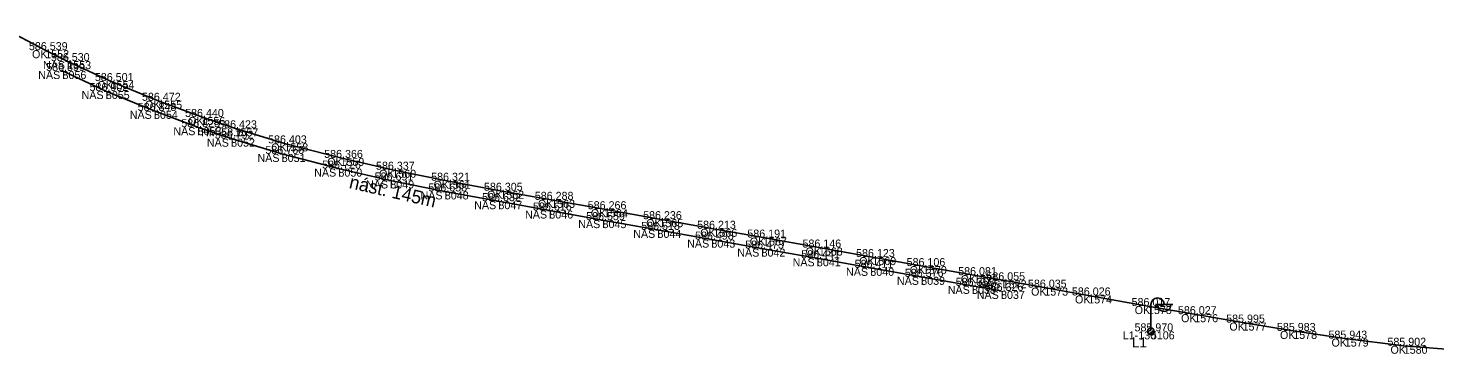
# Model space of a CAD drawing. Extents: x -631472 to -620808, y -1122356 to -1115125.
# Drawn here: x -623891.4 to -623680.4, y -1119630.6 to -1119581.7 of the extents above; entities that cross this region are included whole.
import ezdxf

# ---------------------------------------------------------------- set-up
doc = ezdxf.new("R2010")
doc.units = 0
for name, color, linetype in [('Vrstva 1', 7, 'Continuous'), ('Vrstva 14', 7, 'Continuous'), ('Vrstva 25', 7, 'Continuous'), ('Vrstva 26', 7, 'Continuous'), ('Vrstva 60', 7, 'Continuous'), ('Vrstva 61', 7, 'Continuous'), ('Vrstva 62', 7, 'Continuous')]:
    doc.layers.add(name, color=color, linetype=linetype)

msp = doc.modelspace()

# ---------------------------------------------------------------- linework, layer by layer
at = {"layer": 'Vrstva 1'}
msp.add_lwpolyline([(-623895.04, -1119581.75), (-623888.79, -1119585.05), (-623885.5, -1119586.69), (-623879, -1119589.68), (-623871.85, -1119592.64), (-623865.38, -1119595.06), (-623860.42, -1119596.76), (-623852.94, -1119599.02), (-623844.53, -1119601.2), (-623836.76, -1119602.97), (-623828.58, -1119604.62), (-623820.57, -1119606.12), (-623812.94, -1119607.48), (-623805.01, -1119608.89), (-623796.71, -1119610.38), (-623788.61, -1119611.82), (-623781.17, -1119613.14), (-623772.81, -1119614.63), (-623764.78, -1119616.06), (-623757.2, -1119617.41), (-623749.56, -1119618.77), (-623745.24, -1119619.54), (-623739.01, -1119620.64), (-623732.42, -1119621.81), (-623723.47, -1119623.4), (-623716.52, -1119624.62), (-623709.28, -1119625.88), (-623701.68, -1119627.13), (-623693.95, -1119628.28), (-623685.11, -1119629.35), (-623676.9, -1119629.99)], dxfattribs=at)
at = {"layer": 'Vrstva 14'}
msp.add_lwpolyline([(-623886.21, -1119588.17), (-623879.71, -1119591.17), (-623872.49, -1119594.15), (-623865.95, -1119596.59), (-623860.93, -1119598.31), (-623853.34, -1119600.6), (-623844.84, -1119602.8), (-623837.06, -1119604.58), (-623828.89, -1119606.22), (-623820.85, -1119607.68), (-623813.22, -1119609.08), (-623805.24, -1119610.52), (-623797, -1119611.98), (-623788.92, -1119613.44), (-623781.4, -1119614.79), (-623773.1, -1119616.24), (-623765.09, -1119617.67), (-623757.46, -1119619.02), (-623749.84, -1119620.37), (-623745.49, -1119621.13)], dxfattribs=at)
at = {"layer": 'Vrstva 25'}
for p, q in [((-623723.03, -1119626.69), (-623723.03, -1119623.19)), ((-623722.33, -1119623.19), (-623719.73, -1119623.19)), ((-623723.51, -1119627.34), (-623722.89, -1119626.72)), ((-623723.27, -1119627.63), (-623722.59, -1119626.95))]:
    msp.add_line(p, q, dxfattribs=at)
msp.add_circle((-623723.03, -1119627.19), 0.5, dxfattribs=at)
for centre, start, end in [((-623722.03, -1119623.19), 0, 180), ((-623721.03, -1119623.21), 179.2974, 0.7026)]:
    msp.add_arc(centre, 1, start, end, dxfattribs=at)
at = {"layer": 'Vrstva 60'}
for p, q in [((-623888.79, -1119585.05), (-623888.79, -1119585.05)), ((-623885.5, -1119586.69), (-623885.5, -1119586.69)), ((-623886.21, -1119588.17), (-623886.21, -1119588.17)), ((-623879, -1119589.68), (-623879, -1119589.68)), ((-623879.71, -1119591.17), (-623879.71, -1119591.17)), ((-623871.85, -1119592.64), (-623871.85, -1119592.64)), ((-623872.49, -1119594.15), (-623872.49, -1119594.15)), ((-623865.38, -1119595.06), (-623865.38, -1119595.06)), ((-623865.95, -1119596.59), (-623865.95, -1119596.59)), ((-623860.42, -1119596.76), (-623860.42, -1119596.76)), ((-623860.93, -1119598.31), (-623860.93, -1119598.31)), ((-623852.94, -1119599.02), (-623852.94, -1119599.02)), ((-623853.34, -1119600.6), (-623853.34, -1119600.6)), ((-623844.53, -1119601.2), (-623844.53, -1119601.2)), ((-623844.84, -1119602.8), (-623844.84, -1119602.8)), ((-623836.76, -1119602.97), (-623836.76, -1119602.97)), ((-623837.06, -1119604.58), (-623837.06, -1119604.58)), ((-623828.58, -1119604.62), (-623828.58, -1119604.62)), ((-623828.89, -1119606.22), (-623828.89, -1119606.22)), ((-623820.85, -1119607.68), (-623820.85, -1119607.68)), ((-623820.57, -1119606.12), (-623820.57, -1119606.12)), ((-623812.94, -1119607.48), (-623812.94, -1119607.48)), ((-623813.22, -1119609.08), (-623813.22, -1119609.08)), ((-623805.01, -1119608.89), (-623805.01, -1119608.89)), ((-623805.24, -1119610.52), (-623805.24, -1119610.52)), ((-623797, -1119611.98), (-623797, -1119611.98)), ((-623796.71, -1119610.38), (-623796.71, -1119610.38)), ((-623788.61, -1119611.82), (-623788.61, -1119611.82)), ((-623788.92, -1119613.44), (-623788.92, -1119613.44)), ((-623781.17, -1119613.14), (-623781.17, -1119613.14)), ((-623781.4, -1119614.79), (-623781.4, -1119614.79)), ((-623773.1, -1119616.24), (-623773.1, -1119616.24)), ((-623772.81, -1119614.63), (-623772.81, -1119614.63)), ((-623764.78, -1119616.06), (-623764.78, -1119616.06)), ((-623765.09, -1119617.67), (-623765.09, -1119617.67)), ((-623757.2, -1119617.41), (-623757.2, -1119617.41)), ((-623757.46, -1119619.02), (-623757.46, -1119619.02)), ((-623749.84, -1119620.37), (-623749.84, -1119620.37)), ((-623749.56, -1119618.77), (-623749.56, -1119618.77)), ((-623745.24, -1119619.54), (-623745.24, -1119619.54)), ((-623745.49, -1119621.13), (-623745.49, -1119621.13)), ((-623739.01, -1119620.64), (-623739.01, -1119620.64)), ((-623732.42, -1119621.81), (-623732.42, -1119621.81)), ((-623723.47, -1119623.4), (-623723.47, -1119623.4)), ((-623716.52, -1119624.62), (-623716.52, -1119624.62)), ((-623709.28, -1119625.88), (-623709.28, -1119625.88)), ((-623701.68, -1119627.13), (-623701.68, -1119627.13)), ((-623693.95, -1119628.28), (-623693.95, -1119628.28)), ((-623685.11, -1119629.35), (-623685.11, -1119629.35))]:
    msp.add_line(p, q, dxfattribs=at)

# ---------------------------------------------------------------- texts
at = {"layer": 'Vrstva 14'}
msp.add_text('nást. 145m', height=2, rotation=347.1016, dxfattribs=at).set_placement((-623843.35, -1119605.7))
at = {"layer": 'Vrstva 26'}
msp.add_text('L1', height=1.5, dxfattribs=at).set_placement((-623725.86, -1119629.61))
at = {"layer": 'Vrstva 60'}
for s, p in [('1552', (-623888.79, -1119586.25)), ('1553', (-623885.5, -1119587.89)), ('8056', (-623886.21, -1119589.37)), ('1554', (-623879, -1119590.88)), ('8055', (-623879.71, -1119592.37)), ('1555', (-623871.85, -1119593.84)), ('8054', (-623872.49, -1119595.34)), ('1556', (-623865.38, -1119596.26)), ('8053', (-623865.95, -1119597.79)), ('1557', (-623860.42, -1119597.96)), ('8052', (-623860.93, -1119599.51)), ('1558', (-623852.94, -1119600.22)), ('8051', (-623853.34, -1119601.8)), ('1559', (-623844.53, -1119602.4)), ('8050', (-623844.84, -1119604)), ('1560', (-623836.76, -1119604.17)), ('8049', (-623837.06, -1119605.78)), ('1561', (-623828.58, -1119605.82)), ('8048', (-623828.89, -1119607.42)), ('8047', (-623820.85, -1119608.88)), ('1562', (-623820.57, -1119607.32)), ('1563', (-623812.94, -1119608.68)), ('8046', (-623813.22, -1119610.28)), ('1564', (-623805.01, -1119610.09)), ('8045', (-623805.24, -1119611.72)), ('8044', (-623797, -1119613.18)), ('1565', (-623796.71, -1119611.58)), ('1566', (-623788.61, -1119613.02)), ('8043', (-623788.92, -1119614.64)), ('1567', (-623781.17, -1119614.34)), ('8042', (-623781.4, -1119615.99)), ('8041', (-623773.1, -1119617.44)), ('1568', (-623772.81, -1119615.83)), ('1569', (-623764.78, -1119617.26)), ('8040', (-623765.09, -1119618.87)), ('1570', (-623757.2, -1119618.61)), ('8039', (-623757.46, -1119620.22)), ('8038', (-623749.84, -1119621.57)), ('1571', (-623749.56, -1119619.97)), ('1572', (-623745.24, -1119620.74)), ('8037', (-623745.49, -1119622.33)), ('1573', (-623739.01, -1119621.84)), ('1574', (-623732.42, -1119623.01)), ('1575', (-623723.47, -1119624.6)), ('1576', (-623716.52, -1119625.82)), ('1577', (-623709.28, -1119627.08)), ('5106', (-623723.03, -1119628.39)), ('1578', (-623701.68, -1119628.33)), ('1579', (-623693.95, -1119629.48)), ('1580', (-623685.11, -1119630.55))]:
    msp.add_text(s, height=1.2, dxfattribs=at).set_placement(p)
at = {"layer": 'Vrstva 61'}
for s, p in [('586.539', (-623891.25, -1119585.05)), ('586.530', (-623887.95, -1119586.69)), ('586.899', (-623888.66, -1119588.17)), ('586.501', (-623881.36, -1119589.68)), ('586.902', (-623882.16, -1119591.17)), ('586.848', (-623874.94, -1119594.15)), ('586.472', (-623874.3, -1119592.64)), ('586.440', (-623867.83, -1119595.06)), ('586.825', (-623868.4, -1119596.59)), ('586.792', (-623863.38, -1119598.31)), ('586.423', (-623862.87, -1119596.76)), ('586.766', (-623855.79, -1119600.6)), ('586.403', (-623855.39, -1119599.02)), ('586.726', (-623847.29, -1119602.8)), ('586.366', (-623846.98, -1119601.2)), ('586.691', (-623839.41, -1119604.58)), ('586.337', (-623839.21, -1119602.97)), ('586.321', (-623830.94, -1119604.62)), ('586.658', (-623831.35, -1119606.22)), ('586.305', (-623823.02, -1119606.12)), ('586.632', (-623823.3, -1119607.68)), ('586.616', (-623815.67, -1119609.08)), ('586.288', (-623815.4, -1119607.48)), ('586.266', (-623807.46, -1119608.89)), ('586.559', (-623807.7, -1119610.52)), ('586.236', (-623799.16, -1119610.38)), ('586.518', (-623799.45, -1119611.98)), ('586.213', (-623791.06, -1119611.82)), ('586.191', (-623783.53, -1119613.14)), ('586.498', (-623791.37, -1119613.44)), ('586.473', (-623783.85, -1119614.79)), ('586.146', (-623775.26, -1119614.63)), ('586.441', (-623775.45, -1119616.24)), ('586.123', (-623767.23, -1119616.06)), ('586.106', (-623759.65, -1119617.41)), ('586.411', (-623767.44, -1119617.67)), ('586.376', (-623759.92, -1119619.02)), ('586.081', (-623751.92, -1119618.77)), ('586.055', (-623747.69, -1119619.54)), ('586.353', (-623752.29, -1119620.37)), ('586.326', (-623747.94, -1119621.13)), ('586.035', (-623741.46, -1119620.64)), ('586.026', (-623734.87, -1119621.81)), ('586.017', (-623725.92, -1119623.4)), ('586.027', (-623718.97, -1119624.62)), ('585.995', (-623711.74, -1119625.88)), ('585.970', (-623725.48, -1119627.19)), ('585.983', (-623704.13, -1119627.13)), ('585.943', (-623696.4, -1119628.28)), ('585.902', (-623687.56, -1119629.35))]:
    msp.add_text(s, height=1.2, dxfattribs=at).set_placement(p)
at = {"layer": 'Vrstva 62'}
for s, p in [('OK', (-623890.78, -1119586.25)), ('NAST', (-623889.14, -1119587.89)), ('NAST', (-623889.85, -1119589.37)), ('OK', (-623880.98, -1119590.88)), ('NAST', (-623883.35, -1119592.37)), ('OK', (-623873.84, -1119593.84)), ('NAST', (-623876.13, -1119595.34)), ('OK', (-623867.36, -1119596.26)), ('NAST', (-623869.59, -1119597.79)), ('HM-58.1', (-623865.44, -1119597.96)), ('NAST', (-623864.57, -1119599.51)), ('OK', (-623854.92, -1119600.22)), ('NAST', (-623856.98, -1119601.8)), ('OK', (-623846.52, -1119602.4)), ('NAST', (-623848.48, -1119604)), ('OK', (-623838.74, -1119604.17)), ('NAST', (-623840.7, -1119605.78)), ('OK', (-623830.57, -1119605.82)), ('NAST', (-623832.53, -1119607.42)), ('NAST', (-623824.49, -1119608.88)), ('OK', (-623822.55, -1119607.32)), ('OK', (-623814.93, -1119608.68)), ('NAST', (-623816.86, -1119610.28)), ('OK', (-623807, -1119610.09)), ('NAST', (-623808.88, -1119611.72)), ('NAST', (-623800.64, -1119613.18)), ('OK', (-623798.7, -1119611.58)), ('OK', (-623790.6, -1119613.02)), ('NAST', (-623792.55, -1119614.64)), ('OK', (-623783.16, -1119614.34)), ('NAST', (-623785.04, -1119615.99)), ('NAST', (-623776.74, -1119617.44)), ('OK', (-623774.8, -1119615.83)), ('OK', (-623766.76, -1119617.26)), ('NAST', (-623768.73, -1119618.87)), ('OK', (-623759.19, -1119618.61)), ('NAST', (-623761.1, -1119620.22)), ('NAST', (-623753.48, -1119621.57)), ('OK', (-623751.54, -1119619.97)), ('NAST', (-623748.88, -1119620.74)), ('NAST', (-623749.13, -1119622.33)), ('OK', (-623740.99, -1119621.84)), ('OK', (-623734.4, -1119623.01)), ('OK', (-623725.45, -1119624.6)), ('OK', (-623718.5, -1119625.82)), ('OK', (-623711.26, -1119627.08)), ('L1-130', (-623727.24, -1119628.39)), ('OK', (-623703.67, -1119628.33)), ('OK', (-623695.94, -1119629.48)), ('OK', (-623687.1, -1119630.55))]:
    msp.add_text(s, height=1.2, dxfattribs=at).set_placement(p)

doc.saveas('drawing.dxf')
